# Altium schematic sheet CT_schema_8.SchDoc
size 278 x 170 mm
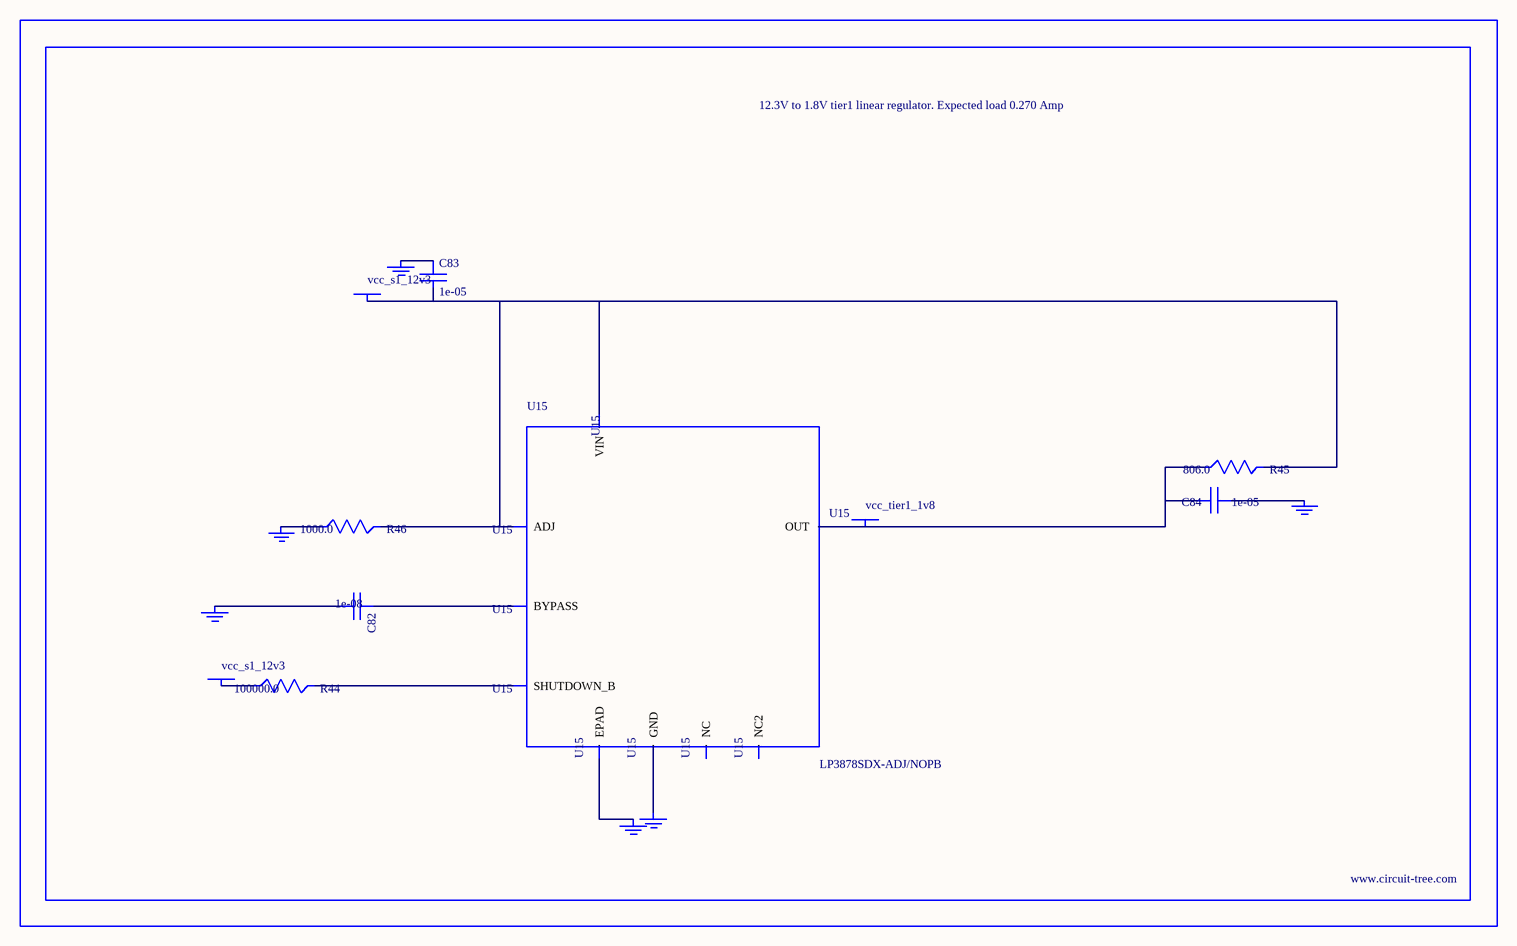
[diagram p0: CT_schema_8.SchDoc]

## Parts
BORDER7  (no value)
C82  1e-08  [C0402]
C83  1e-05  [C1210]
C84  1e-05  [C0805]
GND_INSTANCE_7_0  (no value)
GND_INSTANCE_7_1  (no value)
GND_INSTANCE_7_2  (no value)
GND_INSTANCE_7_3  (no value)
GND_INSTANCE_7_4  (no value)
GND_INSTANCE_7_5  (no value)
POWER_INSTANCE_7_0  vcc_s1_12v3
POWER_INSTANCE_7_1  vcc_s1_12v3
POWER_INSTANCE_7_2  vcc_tier1_1v8
R44  100000.0  [R0603]
R45  806.0  [R0603]
R46  1000.0  [R0603]
U15  LP3878SDX-ADJ/NOPB  [WSON-8]

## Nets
NetC82_1: C82.1 U15.1(BYPASS)
NetC82_2: C82.2 GND_INSTANCE_7_0.0(GND)
NetC83_1: C83.1 GND_INSTANCE_7_1.0(GND)
NetC83_2: C83.2 POWER_INSTANCE_7_0.0(PWR) R45.2 R46.2 U15.4(VIN) U15.6(ADJ)
NetC84_1: C84.1 GND_INSTANCE_7_2.0(GND)
NetC84_2: C84.2 POWER_INSTANCE_7_2.0(PWR) R45.1 U15.5(OUT)
NetGND_INSTANCE_7_3_0: GND_INSTANCE_7_3.0(GND) R46.1
NetGND_INSTANCE_7_4_0: GND_INSTANCE_7_4.0(GND) U15.PAD(EPAD)
NetGND_INSTANCE_7_5_0: GND_INSTANCE_7_5.0(GND) U15.3(GND)
NetPOWER_INSTANCE_7_1_0: POWER_INSTANCE_7_1.0(PWR) R44.1
NetR44_2: R44.2 U15.8(SHUTDOWN_B)

Not connected (* = marked no-connect by the designer): U15 2(NC) 7(NC2)

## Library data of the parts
BORDER7 = BORDER_PAGE7
C82 = C0402C103K3RAC
C83 = C1210C106K5PACTU
C84 = GRM219R60J106ME19D
GND_INSTANCE_7_0-GND_INSTANCE_7_5 = GND
POWER_INSTANCE_7_0-POWER_INSTANCE_7_2 = PWR
R44 = RC0603JR-07100KL
R45 = ERJ-3EKF8060V
R46 = RC0603JR-071KL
